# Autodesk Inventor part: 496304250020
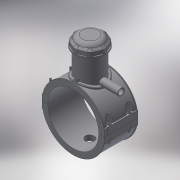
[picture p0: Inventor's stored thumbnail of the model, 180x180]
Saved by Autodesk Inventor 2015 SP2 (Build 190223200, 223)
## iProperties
Created: 2017-07
Part Number: 496304250020
Material: Generic
Description: PLASSON TAPPING SADDLE 250x20
Document SubType Name: Modeling
Designer: KIM
Mass: 1940.22 g
Surface Area: 3747.58 cm^2
Volume: 1940.22 cm^3
Density: 1 g/cm^3
Appearance: Default
Author: KIM
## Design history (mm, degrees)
derived "496304.ipt"
feature "Solid1::496304.ipt"
feature "Solid2::496304.ipt"
feature "Solid4::496304.ipt"
feature "Solid5::496304.ipt"
tag "TaggingFeature1" dims "B_" = 252
body "Solid1"
body "Solid2"
other parameters: "L_" = 176, "d_t" = 6, "H_2" = 177, "H_" = 125, "d1" = 285, "d148" = 3.75, "d160" = 3.75, "d169" = 3.75, "d192" = 7, "d2" = 327.6, "d3" = 62.5, "d4" = 176, "d5" = 0, "d6" = 0.1, "d8" = 0, "d19" = 6, "d20" = 6, "d21" = 105.6, "d23" = 0, "d24" = 52.8, "d26" = 0, "d29" = 3, "d30" = 83.33333, "d31" = 6, "d32" = 0, "d33" = 0, "d34" = 0.6, "d40" = 148.2, "d43" = 0, "d45" = 0, "d47" = 248.1, "d70" = 15, "d72" = 0, "d73" = 6, "d75" = 5, "d76" = 0, "d77" = 12.5, "d78" = 155, "d79" = 15, "d80" = 70.4, "d82" = 5 deg, "d84" = 4, "d85" = 14, "d86" = 0, "d87" = 3, "d88" = 0, "d89" = 1, "d90" = 1, "d91" = 140.8, "d92" = 0, "d93" = 0.5, "d94" = 131.57895, "d96" = 290.7, "d97" = 3.52, "d98" = 0, "d102" = 2.5, "d120" = 140 deg, "d121" = 24.228, "d122" = 20 deg, "d124" = 171, "d126" = 0, "d143" = 257.5, "d145" = 26.92308, "d149" = 3.75, "d150" = 29.61538, "d153" = 176, "d154" = 0, "d156" = 142.5, "d157" = 160 deg, "d159" = 7, "d161" = 3.75, "d162" = 105.6, "d163" = 0, "d164" = 125, "d167" = 25, "d168" = 139.02439, "d170" = 3.75, "d172" = 0, "d173" = 1, "d175" = 125, "d176" = 20 deg, "d177" = 17.5, "d178" = 35, "d180" = 0, "d183" = 14, "d184" = 14, "d185" = 57.2, "d186" = 57.2, "d187" = 142.5, "d188" = 10.5, "d189" = 17.5, "d190" = 0, "d191" = 213.75, "d193" = 7, "d194" = 6.16, "d195" = 90 deg, "d197" = 0, "d199" = 0, "d200" = 17.5, "d202" = 0, "d203" = 177, "d204" = 95, "d206" = 85, "d207" = 132.75, "d208" = 138.06, "d209" = 164.61, "d210" = 86, "d213" = 36, "d216" = 0, "d217" = 25, "d218" = 25, "d219" = 5, "d224" = 0, "d230" = 5, "d233" = 6, "d236" = 126, "d237" = 52.8, "d238" = 6.02433, "d240" = 52.8, "d241" = 52.8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
